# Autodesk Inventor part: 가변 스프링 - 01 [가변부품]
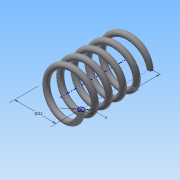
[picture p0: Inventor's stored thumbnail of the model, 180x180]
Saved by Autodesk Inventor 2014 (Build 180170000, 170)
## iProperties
Created: 2015-09
Part Number: 가변 스프링 - 01 [가변부품]
Material: 강철, 탄소
Document SubType Name: Modeling
Designer: study
Density: 1 g/cm^3
Appearance: 반연마
Author: study
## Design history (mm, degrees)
sketch "스케치1"
  geometry: L1 (0, 0)-(11, 0); L2 (11, 0)-(11, 25.508); L3 (11, 25.508)-(0, 25.508); L4 (0, 25.508)-(0, 0); C1 r 1.5 at (11, 0)
  constraints: 8 end point, 2 parallel, 1 centre point, 1 coincident, 1 horizontal, 1 perpendicular
  dimensions: "d0" = 22 diameter of L2 L4; "d1" = 25.50829 distance between parallel lines of L3 L1 (derived); "d2" = 3 diameter of C1
feature "코일1" sketch "스케치1" pitch "d3" = 10; turns "d5" = 5; dims "d4" = 25.50829 (= d1), "d6" = 0, angle "d7" = 90 deg, angle "d8" = 90 deg, "d9" = 0, "d10" = 0
node "작업 평면1"
sketch "스케치2"
  geometry: L1 (-12.5, 0)-(-9.5, 0) reference; L2 (-12.5, 0)-(-9.5, 0) reference; 1 further point
  constraints: 2 horizontal alignment
extrude "돌출1" cut sketch "스케치2" stored distance "d12" = 10; taper "d13" = 0 deg
node "작업 평면2"
sketch "스케치3"
  geometry: L1 (-9.5, 0)-(-12.5, 0) reference; 1 further point
  constraints: 1 horizontal alignment
extrude "돌출2" cut sketch "스케치3" stored distance "d15" = 10; taper "d16" = 0 deg
node "솔리드1"
node "절단 모서리 투영1"
node "절단 모서리 투영2"
node "절단 모서리 투영3"
other parameters: "d11" = 0, "d14" = 25.50829 (= d1)
